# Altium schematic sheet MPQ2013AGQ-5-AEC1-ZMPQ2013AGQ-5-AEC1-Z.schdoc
size 127 x 101 mm
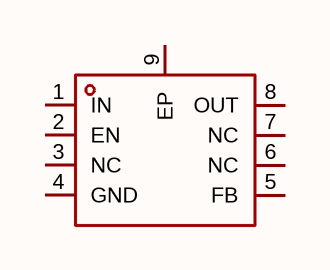
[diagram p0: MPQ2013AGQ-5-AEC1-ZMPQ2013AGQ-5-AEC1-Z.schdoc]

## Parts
U?  mpq2013agq-5-aec1-z  [TDFN-8_L3.0-W3.0-P0.65-BL-EP]  (value not drawn)

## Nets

Not connected (* = marked no-connect by the designer): U? 1(IN) 2(EN) 3(NC) 4(GND) 5(FB) 6(NC) 7(NC) 8(OUT) 9(EP)

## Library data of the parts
U? = mpq2013agq-5-aec1-z: 输出极性:正极;工作电压:40V;输出电压:5V;输出电流:150mA;电源纹波抑制比(PSRR):58dB@(100Hz);输出类型:固定;; Manufacturer: MPS(芯源); AddInBom: yes; ModelId: 52cae27a4bb3417391fd5472d998fec7; ModelName: TDFN-8_L3.0-W3.0-H0.8-P0.65; ModelTransform: 118.8974,118.11,0,90,0,0,0,-0.0005,0; Output Configuration: 正极; Voltage - Supply: 40V; Output Voltage: 5V; Output Current: 150mA; Voltage Dropout: 700mV@(150mA); standby current: 3.3uA; Output Type: 固定; Number of Outputs: 1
